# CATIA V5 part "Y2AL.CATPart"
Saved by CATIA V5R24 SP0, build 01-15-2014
Part number: Y2AL
Bounding box of the stored display mesh (mm): x 0 to 807.313, y -215.345 to 49, z 0 to 2013
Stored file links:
  U:\AREA TECNICA\Documenti\3D sito\BOX\YOUNG 2.0\Y2A\Y2AL.CATPart
  C:\Users\n.rebecchi\diclient\N.REBECCHI\ID_36902_00.CATProduct
  C:\Users\n.rebecchi\diclient\N.REBECCHI\ID_35275_00.CATPart
  C:\Users\n.rebecchi\diclient\N.REBECCHI\ID_38453_00.CATPart
  C:\Users\n.rebecchi\diclient\N.REBECCHI\ID_35871_00.CATPart
  C:\Users\n.rebecchi\diclient\N.REBECCHI\ID_36882_00.CATPart
  C:\Users\n.rebecchi\diclient\N.REBECCHI\ID_14402_03.CATPart
  C:\Users\n.rebecchi\diclient\N.REBECCHI\ID_13308_00.CATPart
  C:\Users\n.rebecchi\diclient\N.REBECCHI\ID_36890_00.CATPart
  C:\Users\n.rebecchi\diclient\N.REBECCHI\ID_35879_02.CATPart
  C:\Users\n.rebecchi\diclient\N.REBECCHI\ID_35274_00.CATPart
  C:\Users\n.rebecchi\diclient\N.REBECCHI\ID_34896_01.CATPart
  C:\Users\n.rebecchi\diclient\N.REBECCHI\ID_38427_00.CATPart
  C:\Users\n.rebecchi\diclient\N.REBECCHI\ID_32899_01.CATPart
  C:\Users\n.rebecchi\diclient\N.REBECCHI\ID_36899_00.CATPart
  C:\Users\n.rebecchi\diclient\N.REBECCHI\ID_35982_00.CATPart
  C:\Users\n.rebecchi\diclient\N.REBECCHI\ID_36441_01.CATPart
  C:\Users\n.rebecchi\diclient\N.REBECCHI\ID_36379_01.CATPart
  C:\Users\n.rebecchi\diclient\N.REBECCHI\ID_475_00.CATPart
  C:\Users\n.rebecchi\diclient\N.REBECCHI\ID_36444_00.CATPart
  C:\Users\n.rebecchi\diclient\N.REBECCHI\ID_36460_00.CATPart
  C:\Users\n.rebecchi\diclient\N.REBECCHI\ID_36463_00.CATPart
  C:\Users\n.rebecchi\diclient\N.REBECCHI\ID_35435_00.CATPart
  C:\Users\n.rebecchi\diclient\N.REBECCHI\ID_35414_00.CATPart
  C:\Users\n.rebecchi\diclient\N.REBECCHI\ID_35439_00.CATPart
  C:\Users\n.rebecchi\diclient\N.REBECCHI\ID_35787_00.CATPart
  C:\Users\n.rebecchi\diclient\N.REBECCHI\ID_35921_00.CATPart
  C:\Users\n.rebecchi\diclient\N.REBECCHI\ID_6944_00.CATPart
  C:\Users\n.rebecchi\diclient\N.REBECCHI\ID_6951_00.CATPart
  C:\Users\n.rebecchi\diclient\N.REBECCHI\ID_6945_01.CATPart
  C:\Users\n.rebecchi\diclient\N.REBECCHI\ID_1788_00.CATPart
  C:\Users\n.rebecchi\diclient\N.REBECCHI\ID_32892_00.CATPart
  C:\Users\n.rebecchi\diclient\N.REBECCHI\ID_19619_00.CATPart
  C:\Users\n.rebecchi\diclient\N.REBECCHI\ID_29078_00.CATPart
  C:\Users\n.rebecchi\diclient\N.REBECCHI\ID_14403_00.CATPart
  C:\Users\n.rebecchi\diclient\N.REBECCHI\ID_9491_00.CATPart
  Z:\3D sito\YOUNG 2.0\BN011B\Files da convertire\BN011B97.CATPart
  C:\Users\n.rebecchi\diclient\N.REBECCHI\ID_36936_00.CATPart
  Z:\3D sito\YOUNG 2.0\BN012G\BN012GSLD.xlsx
  Z:\3D sito\YOUNG 2.0\BN012G\BN012G.xlsx
  Z:\3D sito\YOUNG 2.0\BN011BS\BN011BSD.CATPart
  C:\Users\n.rebecchi\diclient\N.REBECCHI\ID_36512_00.CATProduct
  C:\Users\n.rebecchi\diclient\N.REBECCHI\ID_32956_00.CATPart
  C:\Users\n.rebecchi\diclient\N.REBECCHI\ID_36510_00.CATPart
  C:\Users\n.rebecchi\diclient\N.REBECCHI\ID_36049_02.CATPart
  C:\Users\n.rebecchi\diclient\N.REBECCHI\ID_35330_00.CATPart
  Z:\3D sito\YOUNG 2.0\BN012A\BN012A.xlsx
  U:\AREA TECNICA\Documenti\3D sito\BOX\YOUNG 2.0\Y2A\BN01A.xlsx
  U:\AREA TECNICA\Documenti\3D sito\BOX\YOUNG 2.0\Y2A\BN01AL.xlsx
  U:\AREA TECNICA\Documenti\3D sito\BOX\YOUNG 2.0\Y2R\Y2R.CATPart
  U:\AREA TECNICA\Documenti\3D sito\BOX\YOUNG 2.0\Y2A\Y2AL.xlsx
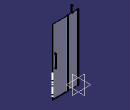
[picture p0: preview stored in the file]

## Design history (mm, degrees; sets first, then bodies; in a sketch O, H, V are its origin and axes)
Parameters
  PartNumber = "Y2A81L" {design table}
  `Larghezza anta` = 429 mm {design table}
  `Larghezza fisso` = 307 mm {design table}
  `Misura nominale.1` = 810 mm {design table}
  LENGTH = 250 mm
Pad1: profile Sketch1.L11, length 1980.5, opposite side length -13.5
Solid1: solid without history
Solid2 "Solido.1": solid without history
Solid3 "Solido.1": solid without history
Pad2: profile Sketch1.L14, length 1994, opposite side length -3
Set1 "GEo"
  Plane1: type Angle, RefPlane xy-plane, Direction sketch element, Angle 90
Body1 "Vetri" (main body)
  Sketch1 on xy-plane, origin (0, 0, 0), H (0, -1, 0), V (1, 0, 0)
    arc A1 centre (-14.7001, 1) radius 1 from (-15.7001, 1) to (-14.7002, 0) ccw
    line L1 (-15.7001, 1) -> (-15.7001, 33.8)
    line L2 (15.7001, 1) -> (15.7001, 33.8)
    line L3 (14.7001, 0) -> (-14.7002, 0)
    arc A2 centre (14.7001, 1) radius 1 from (15.7001, 1) to (14.7001, 0) cw
    arc A3 centre (14.5001, 33.8) radius 1.2 from (14.5001, 35) to (15.7001, 33.8) cw
    arc A4 centre (-14.5001, 33.8) radius 1.2 from (-14.5001, 35) to (-15.7001, 33.8) ccw
    line L4 (3, 779.3038) -> (3, 355.2003)
    construction line L5 (-368.7321, 784.2003) -> (8.5513, 784.2003)
    point P10 (-3, 779.2541)
    arc A5 centre (3.2746, 779.7217) radius 0.5 from (3, 779.3038) to (3.7725, 779.6767) ccw
    line L6 (3.7725, 779.6767) -> (4.1409, 783.7548)
    line L7 (4.1409, 783.7548) -> (4.5355, 786.4228)
    arc A6 centre (0.5783, 787.008) radius 4.0003 from (4.5355, 786.4228) to (3.4069, 789.8367) ccw
    line L8 (3.4069, 789.8367) -> (-2.6006, 795.8442)
    arc A7 centre (-3.8733, 794.5714) radius 1.8 from (-2.6006, 795.8442) to (-5.6673, 794.7182) ccw
    arc A8 centre (10.3119, 793.4106) radius 16.0326 from (-5.6673, 794.7182) to (-5.0303, 788.7562) ccw
    arc A9 centre (4.5415, 791.66) radius 10.0026 from (-5.0303, 788.7562) to (-4.9199, 788.4146) ccw
    arc A10 centre (-21.9649, 782.5681) radius 18.0198 from (-3.9964, 783.9267) to (-4.9199, 788.4146) ccw
    line L9 (-3.9964, 783.9267) -> (-3.6756, 779.684)
    arc A11 centre (-3.177, 779.7217) radius 0.5 from (-3.6756, 779.684) to (-3, 779.2541) ccw
    point P12 (-5.6673, 794.7182)
    point P17 (-4.9199, 788.4146)
    construction line L10 (-26.8635, 822.2284) -> (23.6324, 771.7325)
    line L11 (-3, 355.2003) -> (-3, 779.2541)
    line L12 (3, 331.0003) -> (3, 24.0003)
    line L13 (3, 24.0003) -> (-3, 24.0003)
    line L14 (-3, 24.0003) -> (-3, 331.0003)
    line L15 (-3, 331.0003) -> (3, 331.0003)
    arc A12 centre (0, 352.2003) radius 14 from (12.1813, 345.2998) to (-12.1803, 345.2981) ccw
    construction line L16 (-3, 259.2003) -> (0, 259.2003)
    construction line L17 (0, 259.2003) -> (3, 259.2003)
    line L18 (3, 355.2003) -> (-3, 355.2003)
    construction line L19 (14, 247.3974) -> (14, 224.0003)
    construction arc A13 centre (12.9996, 224.0007) radius 1.0004 from (13, 223.0003) to (14, 224.0003) ccw
    construction line L20 (13, 223.0003) -> (4.2, 223.0003)
    line L21 (12.9996, 319.0003) -> (-12.9996, 319.0003)
    arc A14 centre (-12.9996, 320.0007) radius 1.0004 from (-14, 320.0007) to (-12.9996, 319.0003) ccw
    point P37 (-14, 320.0007)
    line L22 (-14, 320.0007) -> (-14, 343.3974)
    point P38 (-14, 343.3974)
    arc A15 centre (-13, 343.3974) radius 1 from (-12.8259, 344.3822) to (-14, 343.3974) ccw
    line L23 (-14.5001, 35) -> (14.5001, 35)
    arc A16 centre (-12.7194, 344.9926) radius 0.6197 from (-12.8259, 344.3822) to (-12.1803, 345.2981) ccw
    point P43 (-12.8259, 344.3822)
    point P46 (12.8259, 344.3822)
    arc A17 centre (12.7194, 344.9926) radius 0.6197 from (12.8259, 344.3822) to (12.1813, 345.2998) cw
    point P48 (14, 343.3974)
    arc A18 centre (13, 343.3974) radius 1 from (12.8259, 344.3822) to (14, 343.3974) cw
    point P49 (14, 320.0007)
    line L24 (14, 320.0007) -> (14, 343.3974)
    arc A19 centre (12.9996, 320.0007) radius 1.0004 from (14, 320.0007) to (12.9996, 319.0003) cw
    construction line L25 (-15.7001, 0) -> (794.2999, 0)
    point P52 (-15.7001, 0)
    construction line L26 (-15.7001, 0) -> (-15.7001, 810)
    axis line L27 (-15.7001, 810) -> (794.2999, 0)
    curve C1
    radius A3 = 1.2
    radius A4 = 1.2
    distance L1 L2 = 31.4003
    radius A1 = 1
    radius A2 = 1
    length L1 = 32.8 (reference)
    radius A10 = 18.0198
    distance L5 P10 = 4.9462
    radius A11 = 0.5
    radius A5 = 0.5
    angle L6 L7 = 176.7485
    radius A6 = 4.0003
    radius A7 = 1.8
    radius A8 = 16.0326
    radius A9 = 10.0026
    length L8 = 8.4959
    distance L5 A7 = 12.1711
    distance L4 A6 = 1.5786
    angle L6 L4 = 174.8382
    distance L5 A5 = 4.9786
    distance L5 A11 = 4.9786
    length L9 = 4.2548
    length L6 = 4.0947
    distance L5 L18 = 429 {= `Larghezza anta`}
    distance L15 L13 = 307 {= `Larghezza fisso`}
    distance L3 L13 = 24.0003
    distance L3 L23 = 35
    distance L14 L12 = 6
    distance L15 L18 = 24.2
    radius A16 = 0.6197
    distance L15 L21 = 12
    distance L24 L22 = 28
    radius A19 = 1.0004
    radius A18 = 1
    radius A12 = 14
    distance L21 A12 = 47.2
    length L22 = 23.3967
    angle L4 L8 = 45
    distance L5 P12 = 10.5179
    distance L5 P17 = 4.2144
    distance L8 L10 = 1.5
    length L26 = 810 {= `Misura nominale.1`}
    length L25 = 810 {= `Misura nominale.1`}
    tangency: A3 L2, A4 L1, A2 L2, A2 L3, L1 A1, L3 A1, A8 A7, A10 A9, A9 A8, A10 L9, A11 L9, A5 L6, L7 A6, A6 L8, A7 L8, L23 A4, A16 A15, A16 A12, A19 L21, A14 L21, A14 L22, A19 L24, A18 L24, A12 A17, A18 A17, L25 A2, L26 A4
    symmetry: L1 L2 V, L14 L12 V, P43 P46 V, A16 A17 V, P38 P48 V, A15 A18 V, P37 P49 V, L22 L24 V, A14 A19 V
    coincidence: L3 H, L4 L12, L11 L14, P52 L1, P52 H
    horizontal: L5 H, L23 H
Body2 "Maniglia"
Body3
  Sketch2 on yz-plane, origin (0, 0, 0), H (0, 1, 0), V (0, 0, 1)
    line L1 (4.0128, 0) -> (4.0128, 5.7996)
    arc A1 centre (5.0132, 5.7996) radius 1.0004 from (5.0128, 6.8) to (4.0128, 5.7996) ccw
    line L2 (5.0128, 6.8) -> (12.0124, 6.8)
    arc A2 centre (12.0124, 5.7996) radius 1.0004 from (13.0128, 5.8) to (12.0124, 6.8) ccw
    line L3 (13.0128, 5.8) -> (13.0128, 0)
    line L4 (13.0128, 0) -> (4.0128, 0)
    distance H L2 = 6.8
    radius A1 = 1.0004
    radius A2 = 1.0004
    distance L4 H = 0
    distance L1 L3 = 9
    distance L1 V = 4.0128
    tangency: A1 L2, A1 L1, A2 L2, A2 L3
  Pad3: profile Sketch2, direction (1, 0, 0), up to element of Sketch1, opposite side up to face of Pad5 from Sketch4.L21
Body4 "Barra di sostegno"
  Body5 "10001LOU.1\\50003LVR.1\\50003LVR\\PartBody"
    RemoveFace1: RemoveFaces (face of Solid3; face of Solid3; face of Solid3; face of Solid3)
    Body6 "Barra.1\\PartBody"
      Sketch3, origin (174.0984, -468.4895, 1998), H (0.9339, 0.3577, 0), V (-0.3577, 0.9339, 0)
        construction line L1 (-44.8228, 316.6188) -> (161.0862, 407.3188)
        line L2 (-49.8617, 328.0582) -> (156.0473, 418.7582)
        line L3 (166.1251, 395.8794) -> (-39.7839, 305.1794)
        arc A1 centre (161.0862, 407.3188) radius 12.5 from (156.0473, 418.7582) to (166.1251, 395.8794) cw
        arc A2 centre (-44.8228, 316.6188) radius 12.5 from (-39.7839, 305.1794) to (-49.8617, 328.0582) cw
        radius A2 = 12.5
        radius A1 = 12.5
        distance A1 A2 = 250 {= LENGTH}
        distance A2 V = 32.3228
        distance A1 H = 419.8188
        tangency: A1 L2, A2 L2, A1 L3, A2 L3
      Pad4: profile Sketch3, direction (0, 0, 1), length -6
    Add1: tool Body6
    Body7 "10001LOU.1\\50002LVR.1\\50002LVR.1\\PartBody"
      RemoveFace2: RemoveFaces (face of Solid2; face of Solid2; face of Solid2; face of Solid2; face of Solid2; face of Solid2; face of Solid2; face of Solid2; face of Solid2; face of Solid2; face of Solid2; face of Solid2; face of Solid2; face of Solid2; face of Solid2; face of Solid2; face of Solid2; face of Solid2; face of Solid2; face of Solid2; face of Solid2; face of Solid2; face of Solid2; face of Solid2; face of Solid2; face of Solid2; face of Solid2; face of Solid2)
      RemoveFace3: RemoveFaces (face of Solid2; face of Solid2)
    Add2: tool Body7
  Add3: tool Body5
Body8 "Profili"
  Sketch4 on xy-plane, origin (0, 0, 0), H (0, -1, 0), V (1, 0, 0)
    arc A1 centre (-14.7001, 1) radius 1 from (-15.7001, 1) to (-14.7002, 0) ccw
    line L1 (-15.7001, 1) -> (-15.7001, 33.8)
    line L2 (15.7001, 1) -> (15.7001, 33.8)
    line L3 (14.7001, 0) -> (-14.7002, 0)
    arc A2 centre (14.7001, 1) radius 1 from (15.7001, 1) to (14.7001, 0) cw
    arc A3 centre (14.5001, 33.8) radius 1.2 from (14.5001, 35) to (15.7001, 33.8) cw
    arc A4 centre (-14.5001, 33.8) radius 1.2 from (-14.5001, 35) to (-15.7001, 33.8) ccw
    line L4 (3, 779.3038) -> (3, 355.2003)
    construction line L5 (-368.7321, 784.2003) -> (8.5513, 784.2003)
    point P10 (-3, 779.2541)
    arc A5 centre (3.2746, 779.7217) radius 0.5 from (3, 779.3038) to (3.7725, 779.6767) ccw
    line L6 (3.7725, 779.6767) -> (4.1409, 783.7548)
    line L7 (4.1409, 783.7548) -> (4.5355, 786.4228)
    arc A6 centre (0.5783, 787.008) radius 4.0003 from (4.5355, 786.4228) to (3.4069, 789.8367) ccw
    line L8 (3.4069, 789.8367) -> (-2.6006, 795.8442)
    arc A7 centre (-3.8733, 794.5714) radius 1.8 from (-2.6006, 795.8442) to (-5.6673, 794.7182) ccw
    arc A8 centre (10.3119, 793.4106) radius 16.0326 from (-5.6673, 794.7182) to (-5.0303, 788.7562) ccw
    arc A9 centre (4.5415, 791.66) radius 10.0026 from (-5.0303, 788.7562) to (-4.9199, 788.4146) ccw
    arc A10 centre (-21.9649, 782.5681) radius 18.0198 from (-3.9964, 783.9267) to (-4.9199, 788.4146) ccw
    line L9 (-3.9964, 783.9267) -> (-3.6756, 779.684)
    arc A11 centre (-3.177, 779.7217) radius 0.5 from (-3.6756, 779.684) to (-3, 779.2541) ccw
    point P12 (-5.6673, 794.7182)
    point P17 (-4.9199, 788.4146)
    construction line L10 (-26.8635, 822.2284) -> (23.6324, 771.7325)
    line L11 (-3, 355.2003) -> (-3, 779.2541)
    line L12 (3, 331.0003) -> (3, 24.0003)
    line L13 (3, 24.0003) -> (-3, 24.0003)
    line L14 (-3, 24.0003) -> (-3, 331.0003)
    line L15 (-3, 331.0003) -> (3, 331.0003)
    arc A12 centre (0, 352.2003) radius 14 from (12.1813, 345.2998) to (-12.1803, 345.2981) ccw
    construction line L16 (-3, 259.2003) -> (0, 259.2003)
    construction line L17 (0, 259.2003) -> (3, 259.2003)
    line L18 (3, 355.2003) -> (-3, 355.2003)
    construction line L19 (14, 247.3974) -> (14, 224.0003)
    construction arc A13 centre (12.9996, 224.0007) radius 1.0004 from (13, 223.0003) to (14, 224.0003) ccw
    construction line L20 (13, 223.0003) -> (4.2, 223.0003)
    line L21 (12.9996, 319.0003) -> (-12.9996, 319.0003)
    arc A14 centre (-12.9996, 320.0007) radius 1.0004 from (-14, 320.0007) to (-12.9996, 319.0003) ccw
    point P37 (-14, 320.0007)
    line L22 (-14, 320.0007) -> (-14, 343.3974)
    point P38 (-14, 343.3974)
    arc A15 centre (-13, 343.3974) radius 1 from (-12.8259, 344.3822) to (-14, 343.3974) ccw
    line L23 (-14.5001, 35) -> (14.5001, 35)
    arc A16 centre (-12.7194, 344.9926) radius 0.6197 from (-12.8259, 344.3822) to (-12.1803, 345.2981) ccw
    point P43 (-12.8259, 344.3822)
    point P46 (12.8259, 344.3822)
    arc A17 centre (12.7194, 344.9926) radius 0.6197 from (12.8259, 344.3822) to (12.1813, 345.2998) cw
    point P48 (14, 343.3974)
    arc A18 centre (13, 343.3974) radius 1 from (12.8259, 344.3822) to (14, 343.3974) cw
    point P49 (14, 320.0007)
    line L24 (14, 320.0007) -> (14, 343.3974)
    arc A19 centre (12.9996, 320.0007) radius 1.0004 from (14, 320.0007) to (12.9996, 319.0003) cw
    construction line L25 (-15.7001, 0) -> (794.2999, 0)
    point P52 (-15.7001, 0)
    construction line L26 (-15.7001, 0) -> (-15.7001, 810)
    axis line L27 (-15.7001, 810) -> (794.2999, 0)
    curve C1
    radius A3 = 1.2
    radius A4 = 1.2
    distance L1 L2 = 31.4003
    radius A1 = 1
    radius A2 = 1
    length L1 = 32.8 (reference)
    radius A10 = 18.0198
    distance L5 P10 = 4.9462
    radius A11 = 0.5
    radius A5 = 0.5
    angle L6 L7 = 176.7485
    radius A6 = 4.0003
    radius A7 = 1.8
    radius A8 = 16.0326
    radius A9 = 10.0026
    length L8 = 8.4959
    distance L5 A7 = 12.1711
    distance L4 A6 = 1.5786
    angle L6 L4 = 174.8382
    distance L5 A5 = 4.9786
    distance L5 A11 = 4.9786
    length L9 = 4.2548
    length L6 = 4.0947
    distance L5 L18 = 429 {= `Larghezza anta`}
    distance L15 L13 = 307 {= `Larghezza fisso`}
    distance L3 L13 = 24.0003
    distance L3 L23 = 35
    distance L14 L12 = 6
    distance L15 L18 = 24.2
    radius A16 = 0.6197
    distance L15 L21 = 12
    distance L24 L22 = 28
    radius A19 = 1.0004
    radius A18 = 1
    radius A12 = 14
    distance L21 A12 = 47.2
    length L22 = 23.3967
    angle L4 L8 = 45
    distance L5 P12 = 10.5179
    distance L5 P17 = 4.2144
    distance L8 L10 = 1.5
    length L26 = 810 {= `Misura nominale.1`}
    length L25 = 810 {= `Misura nominale.1`}
    tangency: A3 L2, A4 L1, A2 L2, A2 L3, L1 A1, L3 A1, A8 A7, A10 A9, A9 A8, A10 L9, A11 L9, A5 L6, L7 A6, A6 L8, A7 L8, L23 A4, A16 A15, A16 A12, A19 L21, A14 L21, A14 L22, A19 L24, A18 L24, A12 A17, A18 A17, L25 A2, L26 A4
    symmetry: L1 L2 V, L14 L12 V, P43 P46 V, A16 A17 V, P38 P48 V, A15 A18 V, P37 P49 V, L22 L24 V, A14 A19 V
    coincidence: L3 H, L4 L12, L11 L14, P52 L1, P52 H
    horizontal: L5 H, L23 H
  Pad5: profile Sketch4.L2, length 2000
  Body9
    Sketch5 on yz-plane, origin (0, 0, 0), H (0, 1, 0), V (0, 0, 1)
      line L1 (4.0128, 0) -> (4.0128, 5.7996)
      arc A1 centre (5.0132, 5.7996) radius 1.0004 from (5.0128, 6.8) to (4.0128, 5.7996) ccw
      line L2 (5.0128, 6.8) -> (12.0124, 6.8)
      arc A2 centre (12.0124, 5.7996) radius 1.0004 from (13.0128, 5.8) to (12.0124, 6.8) ccw
      line L3 (13.0128, 5.8) -> (13.0128, 0)
      line L4 (13.0128, 0) -> (4.0128, 0)
      distance H L2 = 6.8
      radius A1 = 1.0004
      radius A2 = 1.0004
      distance L4 H = 0
      distance L1 L3 = 9
      distance L1 V = 4.0128
      tangency: A1 L2, A1 L1, A2 L2, A2 L3
    Pad6: profile Sketch5, direction (1, 0, 0), up to element of Sketch4
  Trim1: tool Body9
Relations
  design table "Tabella di progetto.1", configuration 12, drives PartNumber, `Larghezza anta`, `Larghezza fisso`, `Misura nominale.1`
